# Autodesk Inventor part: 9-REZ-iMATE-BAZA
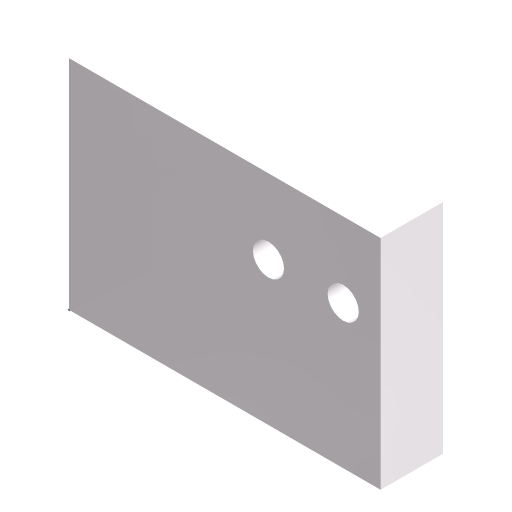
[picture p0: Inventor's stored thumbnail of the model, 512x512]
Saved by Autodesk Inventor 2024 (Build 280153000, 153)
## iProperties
Category: TEST
Company: ATC
Created: 2023-03
Part Number: 9-REZ-iMATE-BAZA
Document SubType Name: Modeling
Designer: Andrzej Jaskulski
Manufacturer: Standard
Standards Organization: Custom
Material: Kurs-AJ
Density: 1 g/cm^3
Appearance: Kurs-AJ
Checked By: A.J.
Engr Approved By: Andrzej Jaskulski
Mfg Approved By: Andrzej Jaskulski
Authority: A.J.
Gb: 805,00000 mm
Hb: 535,00000 mm
Gogz: 24,00000 mm
Hogz: 14,00000 mm
Hoz: 24,00000 mm
Gozz: 12,00000 mm
FiStd: 10,00000 mm
Sb: 1310,00000 mm
m3: m3
Szer: 20,00000 mm
Title: A.J.: Kurs R2024-MEP
Author: Andrzej Jaskulski
Revision Number: 1/24
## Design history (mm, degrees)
sketch "Baza"
  geometry: L1 (0, 0)-(-100, 0); L2 (-100, 0)-(-100, 70); L3 (-100, 70)-(0, 70); L4 (0, 70)-(0, 0); C1 r 5 at (-64, 46); C2 r 5 at (-88, 46)
  constraints: 8 end point, 2 centre point, 2 perpendicular, 1 horizontal, 1 horizontal alignment, 1 parallel, 1 vertical alignment, 1 other
  dimensions: "d3" = 70 distance of L1.end L2.end; "d14" = 24 distance of C2.centre C1.centre; "d15" = 24 distance from line of C2.centre L3 (= Hoz); "d17" = 12 distance from line of C2.centre L2 (= Gozz); "d45" = 100 distance of L1.start L1.end
extrude "Korpus" new body sketch "Baza" distance "d20" = 20; taper "d21" = 0 deg
node "Bryła1"
node "Korpusy bryłowe"
node "Korpusy powierzchniowe"
other parameters: "Gb" = 805 [user parameter], "Hb" = 535 [user parameter], "Gogz" = 24 [user parameter], "Hogz" = 14 [user parameter], "Hoz" = 24 [user parameter; used in 1 equation term], "Gozz" = 12 [user parameter; used in 1 equation term], "FiStd" = 10 [user parameter], "Sb" = 1310 [user parameter], "Szer" = 20 (= d20) [user parameter], "d44" = 0
